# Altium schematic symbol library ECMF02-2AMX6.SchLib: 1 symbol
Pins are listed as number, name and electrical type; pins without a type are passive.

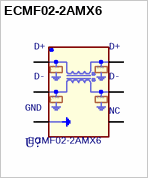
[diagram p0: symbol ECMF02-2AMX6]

## ECMF02-2AMX6
designator U?
footprint ST_QFN50P175X155X55-6L
pins: 1 D+, 2 D-, 3 GND, 4 NC, 5 D-1, 6 D+1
